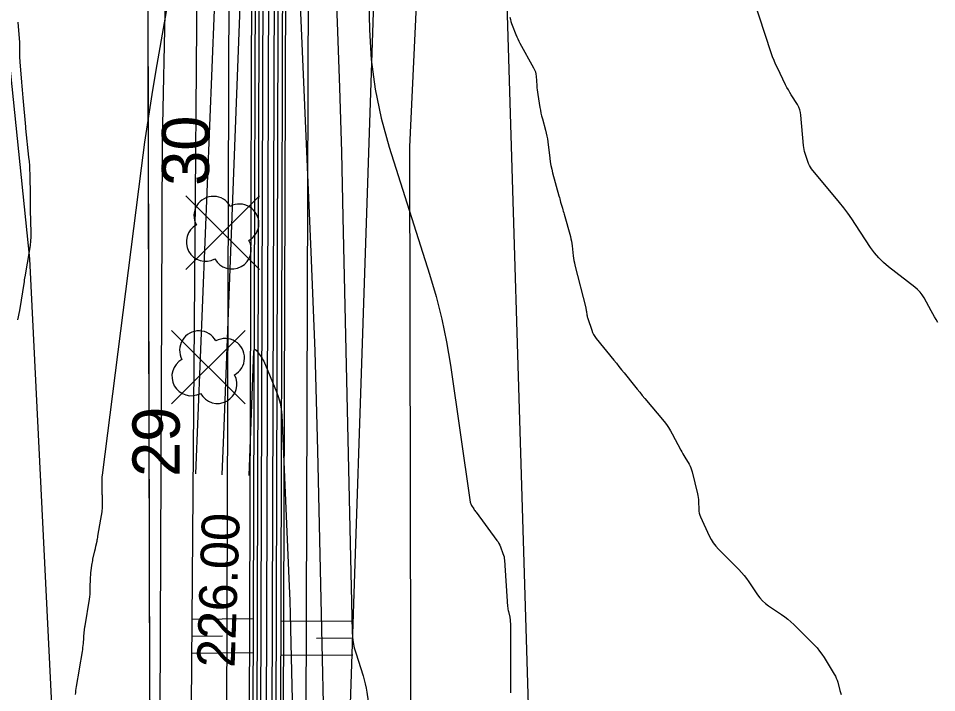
# Model space of a CAD drawing. Extents: x -534410 to -534262, y -1190162 to -1189584.
# Drawn here: x -534372.95 to -534348.66, y -1189778.79 to -1189760.95 of the extents above; entities that cross this region are included whole.
import ezdxf

# ---------------------------------------------------------------- set-up
doc = ezdxf.new("R2010")
doc.units = 0
for name, color, linetype in [('30', 7, 'Continuous'), ('31', 7, 'Continuous'), ('40', 7, 'Continuous'), ('_linie', 7, 'Continuous'), ('_N_osa', 7, 'Continuous'), ('_N_tenká', 7, 'Continuous'), ('_N_tenká_velmi', 7, 'Continuous'), ('_přístup', 7, 'Continuous'), ('_tenka', 7, 'Continuous'), ('_velmi_tenka', 7, 'Continuous'), ('Default', 7, 'Continuous'), ('Hranice parcel', 7, 'Continuous')]:
    doc.layers.add(name, color=color, linetype=linetype)

msp = doc.modelspace()

# ---------------------------------------------------------------- linework, layer by layer
at = {"layer": '30'}
for points in [[(-534367.558, -1189773.027), (-534367.512, -1189771.753), (-534366.662, -1189749.511), (-534366.647, -1189749.405), (-534366.611, -1189749.36), (-534366.556, -1189749.375), (-534366.481, -1189749.452), (-534365.983, -1189750.077), (-534365.978, -1189750.084), (-534365.973, -1189750.092), (-534365.968, -1189750.1), (-534365.964, -1189750.108), (-534365.95, -1189750.142), (-534365.947, -1189750.15), (-534365.945, -1189750.159), (-534365.943, -1189750.168), (-534365.943, -1189750.177), (-534365.213, -1189767.124), (-534365.16, -1189768.439), (-534365.113, -1189769.753), (-534365.074, -1189771.067), (-534365.041, -1189772.382), (-534364.917, -1189777.897), (-534364.89, -1189779.084)], [(-534363.748, -1189757.443), (-534363.663, -1189761.251), (-534363.617, -1189762.041), (-534363.516, -1189762.822), (-534363.358, -1189763.593), (-534363.145, -1189764.355), (-534362.075, -1189767.718), (-534361.899, -1189768.311), (-534361.749, -1189768.91), (-534361.623, -1189769.514), (-534361.522, -1189770.124), (-534360.997, -1189773.751), (-534360.992, -1189773.776), (-534360.984, -1189773.801), (-534360.974, -1189773.824), (-534360.961, -1189773.846), (-534360.903, -1189773.932), (-534360.889, -1189773.954), (-534360.874, -1189773.975), (-534360.859, -1189773.997), (-534360.843, -1189774.018), (-534360.289, -1189774.768), (-534360.262, -1189774.807), (-534360.238, -1189774.848), (-534360.217, -1189774.889), (-534360.199, -1189774.933), (-534360.131, -1189775.109), (-534360.115, -1189775.154), (-534360.103, -1189775.199), (-534360.095, -1189775.245), (-534360.09, -1189775.292), (-534360.007, -1189776.519), (-534360.004, -1189776.552), (-534360, -1189776.585), (-534359.994, -1189776.617), (-534359.987, -1189776.65), (-534359.951, -1189776.798), (-534359.946, -1189776.821), (-534359.942, -1189776.845), (-534359.94, -1189776.869), (-534359.939, -1189776.893), (-534359.936, -1189776.989), (-534359.936, -1189777.013), (-534359.935, -1189777.037), (-534359.935, -1189777.061), (-534359.935, -1189777.085), (-534359.935, -1189778.604), (-534359.935, -1189778.628), (-534359.935, -1189778.652), (-534359.935, -1189778.676), (-534359.934, -1189778.7), (-534359.932, -1189778.799)], [(-534371.442, -1189778.847), (-534371.437, -1189778.793), (-534371.43, -1189778.739), (-534371.423, -1189778.686), (-534371.414, -1189778.632), (-534371.339, -1189778.173), (-534371.338, -1189778.167), (-534371.26, -1189777.71), (-534371.251, -1189777.656), (-534371.244, -1189777.601), (-534371.238, -1189777.546), (-534371.233, -1189777.491), (-534371.21, -1189777.187), (-534371.209, -1189777.174), (-534371.208, -1189777.161), (-534371.206, -1189777.147), (-534371.204, -1189777.134), (-534371.191, -1189777.055), (-534371.187, -1189777.028), (-534371.075, -1189776.323), (-534371.065, -1189776.256), (-534371.058, -1189776.19), (-534371.053, -1189776.123), (-534371.05, -1189776.056), (-534371.041, -1189775.731), (-534371.04, -1189775.692), (-534371.037, -1189775.652), (-534371.034, -1189775.613), (-534371.029, -1189775.574), (-534371.008, -1189775.417), (-534371.002, -1189775.378), (-534370.996, -1189775.339), (-534370.988, -1189775.3), (-534370.98, -1189775.262), (-534370.931, -1189775.044), (-534370.917, -1189774.98), (-534370.902, -1189774.915), (-534370.873, -1189774.786), (-534370.866, -1189774.754), (-534370.859, -1189774.721), (-534370.853, -1189774.689), (-534370.847, -1189774.656), (-534370.798, -1189774.351), (-534370.795, -1189774.334), (-534370.792, -1189774.314), (-534370.79, -1189774.301), (-534370.741, -1189774.013), (-534370.734, -1189773.969), (-534370.73, -1189773.926), (-534370.727, -1189773.882), (-534370.727, -1189773.838), (-534370.732, -1189773.596), (-534370.732, -1189773.573), (-534370.733, -1189773.551), (-534370.733, -1189773.506), (-534370.733, -1189773.484), (-534370.733, -1189773.462), (-534370.738, -1189773.219), (-534370.738, -1189773.175), (-534370.737, -1189773.131), (-534370.734, -1189773.087), (-534370.729, -1189773.043), (-534369.696, -1189764.915), (-534369.604, -1189764.226), (-534369.504, -1189763.539), (-534369.396, -1189762.853), (-534369.28, -1189762.169), (-534368.697, -1189758.85)], [(-534348.626, -1189768.999), (-534348.67, -1189768.922), (-534348.714, -1189768.844), (-534348.757, -1189768.766), (-534348.8, -1189768.689), (-534348.989, -1189768.347), (-534349.038, -1189768.268), (-534349.095, -1189768.194), (-534349.159, -1189768.127), (-534349.23, -1189768.066), (-534349.927, -1189767.528), (-534350.062, -1189767.414), (-534350.187, -1189767.29), (-534350.3, -1189767.156), (-534350.403, -1189767.011), (-534350.799, -1189766.401), (-534350.9, -1189766.251), (-534351.004, -1189766.104), (-534351.113, -1189765.96), (-534351.227, -1189765.819), (-534351.963, -1189764.93), (-534351.996, -1189764.886), (-534352.024, -1189764.839), (-534352.048, -1189764.79), (-534352.067, -1189764.739), (-534352.134, -1189764.527), (-534352.149, -1189764.473), (-534352.161, -1189764.42), (-534352.17, -1189764.365), (-534352.177, -1189764.31), (-534352.246, -1189763.513), (-534352.257, -1189763.438), (-534352.276, -1189763.366), (-534352.304, -1189763.298), (-534352.341, -1189763.232), (-534352.503, -1189762.974), (-534352.542, -1189762.909), (-534352.58, -1189762.843), (-534352.616, -1189762.776), (-534352.651, -1189762.708), (-534352.87, -1189762.261), (-534352.916, -1189762.163), (-534352.958, -1189762.064), (-534352.997, -1189761.963), (-534353.033, -1189761.861), (-534353.994, -1189758.911)]]:
    msp.add_lwpolyline(points, dxfattribs=at)
at = {"layer": '31'}
for points in [[(-534365.123, -1189746.489), (-534365.076, -1189747.773), (-534365.028, -1189749.058), (-534364.976, -1189750.342), (-534364.922, -1189751.626), (-534364.59, -1189759.346), (-534364.52, -1189761.061), (-534364.46, -1189762.776), (-534364.408, -1189764.492), (-534364.365, -1189766.207), (-534364.12, -1189777.185), (-534364.111, -1189777.327), (-534364.093, -1189777.468), (-534364.065, -1189777.607), (-534364.026, -1189777.744), (-534363.833, -1189778.351), (-534363.802, -1189778.458), (-534363.774, -1189778.566), (-534363.752, -1189778.675), (-534363.733, -1189778.785), (-534363.639, -1189779.439)], [(-534368.254, -1189773.003), (-534367.398, -1189751.502), (-534367.341, -1189750.144), (-534367.279, -1189748.788), (-534367.241, -1189748.042)], [(-534359.946, -1189760.921), (-534359.936, -1189760.975), (-534359.923, -1189761.029), (-534359.907, -1189761.081), (-534359.888, -1189761.133), (-534359.79, -1189761.378), (-534359.765, -1189761.436), (-534359.74, -1189761.493), (-534359.712, -1189761.548), (-534359.682, -1189761.603), (-534359.319, -1189762.256), (-534359.293, -1189762.31), (-534359.273, -1189762.365), (-534359.259, -1189762.423), (-534359.252, -1189762.482), (-534359.236, -1189762.724), (-534359.231, -1189762.784), (-534359.225, -1189762.844), (-534359.218, -1189762.904), (-534359.209, -1189762.964), (-534359.155, -1189763.304), (-534359.142, -1189763.38), (-534359.126, -1189763.456), (-534359.108, -1189763.532), (-534359.089, -1189763.606), (-534359.003, -1189763.911), (-534358.984, -1189763.987), (-534358.967, -1189764.063), (-534358.953, -1189764.141), (-534358.942, -1189764.218), (-534358.891, -1189764.649), (-534358.878, -1189764.746), (-534358.861, -1189764.843), (-534358.841, -1189764.939), (-534358.817, -1189765.035), (-534358.65, -1189765.648), (-534358.639, -1189765.689), (-534358.628, -1189765.729), (-534358.616, -1189765.77), (-534358.605, -1189765.81), (-534358.558, -1189765.972), (-534358.546, -1189766.013), (-534358.534, -1189766.053), (-534358.523, -1189766.094), (-534358.512, -1189766.135), (-534358.348, -1189766.72), (-534358.332, -1189766.782), (-534358.319, -1189766.845), (-534358.308, -1189766.909), (-534358.299, -1189766.973), (-534358.271, -1189767.23), (-534358.263, -1189767.294), (-534358.253, -1189767.358), (-534358.24, -1189767.421), (-534358.226, -1189767.484), (-534357.942, -1189768.611), (-534357.936, -1189768.634), (-534357.932, -1189768.658), (-534357.927, -1189768.681), (-534357.924, -1189768.704), (-534357.91, -1189768.798), (-534357.907, -1189768.821), (-534357.902, -1189768.844), (-534357.896, -1189768.867), (-534357.889, -1189768.889), (-534357.783, -1189769.202), (-534357.761, -1189769.26), (-534357.733, -1189769.316), (-534357.701, -1189769.369), (-534357.664, -1189769.419), (-534357.198, -1189769.992), (-534357.13, -1189770.077), (-534357.061, -1189770.162), (-534356.992, -1189770.247), (-534356.924, -1189770.333), (-534356.65, -1189770.674), (-534356.582, -1189770.759), (-534356.513, -1189770.844), (-534356.444, -1189770.929), (-534356.374, -1189771.013), (-534355.869, -1189771.622), (-534355.808, -1189771.7), (-534355.751, -1189771.78), (-534355.699, -1189771.863), (-534355.65, -1189771.949), (-534355.421, -1189772.376), (-534355.396, -1189772.424), (-534355.369, -1189772.471), (-534355.343, -1189772.518), (-534355.316, -1189772.565), (-534355.206, -1189772.751), (-534355.181, -1189772.799), (-534355.159, -1189772.847), (-534355.14, -1189772.898), (-534355.125, -1189772.949), (-534354.982, -1189773.529), (-534354.971, -1189773.58), (-534354.963, -1189773.631), (-534354.957, -1189773.683), (-534354.955, -1189773.735), (-534354.95, -1189773.945), (-534354.947, -1189773.996), (-534354.938, -1189774.047), (-534354.924, -1189774.096), (-534354.904, -1189774.145), (-534354.674, -1189774.646), (-534354.625, -1189774.742), (-534354.567, -1189774.833), (-534354.502, -1189774.919), (-534354.429, -1189774.999), (-534353.891, -1189775.537), (-534353.819, -1189775.612), (-534353.751, -1189775.691), (-534353.687, -1189775.773), (-534353.627, -1189775.858), (-534353.394, -1189776.206), (-534353.332, -1189776.289), (-534353.263, -1189776.365), (-534353.187, -1189776.434), (-534353.104, -1189776.495), (-534352.757, -1189776.728), (-534352.672, -1189776.788), (-534352.59, -1189776.852), (-534352.511, -1189776.92), (-534352.436, -1189776.992), (-534351.892, -1189777.536), (-534351.82, -1189777.612), (-534351.753, -1189777.693), (-534351.691, -1189777.777), (-534351.633, -1189777.865), (-534351.363, -1189778.308), (-534351.335, -1189778.358), (-534351.311, -1189778.409), (-534351.291, -1189778.461), (-534351.274, -1189778.515), (-534351.214, -1189778.735), (-534351.2, -1189778.79), (-534351.186, -1189778.845)], [(-534372.965, -1189768.926), (-534372.949, -1189768.844), (-534372.933, -1189768.762), (-534372.919, -1189768.68), (-534372.794, -1189767.913), (-534372.791, -1189767.892), (-534372.788, -1189767.871), (-534372.782, -1189767.829), (-534372.779, -1189767.808), (-534372.776, -1189767.787), (-534372.65, -1189767.063), (-534372.634, -1189766.954), (-534372.623, -1189766.844), (-534372.618, -1189766.733), (-534372.617, -1189766.623), (-534372.629, -1189766.014), (-534372.63, -1189765.985), (-534372.63, -1189765.957), (-534372.63, -1189765.929), (-534372.63, -1189765.901), (-534372.631, -1189765.789), (-534372.631, -1189765.761), (-534372.631, -1189765.733), (-534372.632, -1189765.705), (-534372.632, -1189765.676), (-534372.645, -1189765.067), (-534372.648, -1189764.956), (-534372.654, -1189764.845), (-534372.663, -1189764.734), (-534372.674, -1189764.624), (-534372.758, -1189763.868), (-534372.758, -1189763.86), (-534372.758, -1189763.852), (-534372.759, -1189763.833), (-534372.759, -1189763.825), (-534372.759, -1189763.821), (-534372.829, -1189763.052), (-534372.838, -1189762.948), (-534372.847, -1189762.844), (-534372.856, -1189762.741), (-534372.864, -1189762.637), (-534372.906, -1189762.098), (-534372.909, -1189762.056), (-534372.911, -1189762.014), (-534372.912, -1189761.972), (-534372.913, -1189761.929), (-534372.913, -1189761.76), (-534372.913, -1189761.717), (-534372.914, -1189761.675), (-534372.916, -1189761.633), (-534372.918, -1189761.59), (-534372.955, -1189761.052)], [(-534366.847, -1189773.051), (-534366.721, -1189769.754), (-534366.716, -1189769.719), (-534366.705, -1189769.705), (-534366.687, -1189769.71), (-534366.663, -1189769.734), (-534366.553, -1189769.873), (-534366.526, -1189769.908), (-534366.503, -1189769.945), (-534366.482, -1189769.983), (-534366.463, -1189770.023), (-534366.123, -1189770.834), (-534366.067, -1189770.984), (-534366.026, -1189771.137), (-534365.998, -1189771.294), (-534365.984, -1189771.453), (-534365.789, -1189775.978), (-534365.774, -1189776.354), (-534365.761, -1189776.729), (-534365.75, -1189777.105), (-534365.74, -1189777.481), (-534365.707, -1189778.983)]]:
    msp.add_lwpolyline(points, dxfattribs=at)
at = {"layer": '_linie'}
for points in [[(-534366.12, -1189620.81), (-534364.52, -1189627.2), (-534365.69, -1189653.8), (-534366.76, -1189684.81), (-534368.14, -1189748.73), (-534368.38, -1189779.14), (-534368.65, -1189820.64), (-534368.59, -1189847.58), (-534367.2, -1189913.8)], [(-534363.12, -1189621.02), (-534362.79, -1189621.58), (-534361.82, -1189627.79), (-534363.46, -1189653.55), (-534365.47, -1189684.77), (-534366.65, -1189748.83), (-534366.75, -1189779.47), (-534366.9, -1189820.47), (-534366.95, -1189846.72), (-534366.338, -1189888.804), (-534363.85, -1189911.95), (-534357.07, -1189929.19), (-534352.334, -1189940.856)], [(-534359.03, -1189621.26), (-534359.41, -1189621.83), (-534360.84, -1189627.76), (-534362.92, -1189653.56), (-534364.64, -1189685), (-534365.94, -1189748.9), (-534366.02, -1189779.52), (-534366.03, -1189820.5), (-534366.48, -1189846.73), (-534365.511, -1189888.873), (-534362.72, -1189912.12), (-534356.62, -1189928.64), (-534351.589, -1189940.594)]]:
    msp.add_lwpolyline(points, dxfattribs=at)
at = {"layer": '_N_osa'}
msp.add_lwpolyline([(-534351.95, -1189940.722), (-534356.845, -1189928.915), (-534363.285, -1189912.035), (-534365.925, -1189888.838), (-534366.715, -1189846.725), (-534366.465, -1189820.485), (-534366.385, -1189779.495), (-534366.295, -1189748.865), (-534365.055, -1189684.885), (-534363.19, -1189653.555), (-534361.333, -1189627.822)], dxfattribs=at)
at = {"layer": '_N_tenká'}
for points in [[(-534352.92, -1189941.124), (-534357.821, -1189929.303), (-534364.313, -1189912.285), (-534366.973, -1189888.908), (-534367.765, -1189846.73), (-534367.515, -1189820.479), (-534367.435, -1189779.492), (-534367.345, -1189748.853), (-534366.104, -1189684.844), (-534364.238, -1189653.486), (-534362.424, -1189628.352), (-534361.782, -1189627.792)], [(-534350.98, -1189940.319), (-534355.869, -1189928.527), (-534362.257, -1189911.785), (-534364.876, -1189888.769), (-534365.665, -1189846.72), (-534365.415, -1189820.491), (-534365.335, -1189779.498), (-534365.245, -1189748.877), (-534364.006, -1189684.926), (-534362.142, -1189653.624), (-534360.329, -1189628.488), (-534360.884, -1189627.851)]]:
    msp.add_lwpolyline(points, dxfattribs=at)
at = {"layer": '_N_tenká_velmi'}
for points in [[(-534352.366, -1189940.894), (-534357.263, -1189929.081), (-534363.726, -1189912.142), (-534366.374, -1189888.868), (-534367.165, -1189846.727), (-534366.915, -1189820.482), (-534366.835, -1189779.494), (-534366.745, -1189748.86), (-534365.505, -1189684.867), (-534363.639, -1189653.525), (-534361.782, -1189627.792)], [(-534352.181, -1189940.817), (-534357.077, -1189929.007), (-534363.53, -1189912.095), (-534366.174, -1189888.855), (-534366.965, -1189846.726), (-534366.715, -1189820.484), (-534366.635, -1189779.494), (-534366.545, -1189748.862), (-534365.305, -1189684.875), (-534363.439, -1189653.539), (-534361.583, -1189627.805)], [(-534352.089, -1189940.779), (-534356.984, -1189928.97), (-534363.432, -1189912.071), (-534366.074, -1189888.848), (-534366.865, -1189846.726), (-534366.615, -1189820.484), (-534366.535, -1189779.495), (-534366.445, -1189748.863), (-534365.205, -1189684.879), (-534363.34, -1189653.545), (-534361.483, -1189627.812)], [(-534351.812, -1189940.664), (-534356.706, -1189928.86), (-534363.138, -1189911.999), (-534365.775, -1189888.828), (-534366.565, -1189846.724), (-534366.315, -1189820.486), (-534366.235, -1189779.495), (-534366.145, -1189748.867), (-534364.905, -1189684.891), (-534363.04, -1189653.565), (-534361.184, -1189627.831)], [(-534351.719, -1189940.626), (-534356.613, -1189928.823), (-534363.04, -1189911.975), (-534365.675, -1189888.822), (-534366.465, -1189846.724), (-534366.215, -1189820.486), (-534366.135, -1189779.496), (-534366.045, -1189748.868), (-534364.805, -1189684.895), (-534362.941, -1189653.571), (-534361.084, -1189627.838)], [(-534351.534, -1189940.549), (-534356.427, -1189928.749), (-534362.844, -1189911.928), (-534365.475, -1189888.808), (-534366.265, -1189846.723), (-534366.015, -1189820.488), (-534365.935, -1189779.496), (-534365.845, -1189748.87), (-534364.605, -1189684.903), (-534362.741, -1189653.585), (-534360.884, -1189627.851)]]:
    msp.add_lwpolyline(points, dxfattribs=at)
at = {"layer": '_přístup'}
for p, q in [((-534366.577, -1189767.593), (-534368.523, -1189765.647)), ((-534368.523, -1189767.593), (-534366.577, -1189765.647)), ((-534366.957, -1189771.153), (-534368.903, -1189769.207)), ((-534368.903, -1189771.153), (-534366.957, -1189769.207))]:
    msp.add_line(p, q, dxfattribs=at)
for centre in [(-534367.55, -1189766.62), (-534367.93, -1189770.18)]:
    msp.add_circle(centre, 0.000512, dxfattribs=at)
for centre, start, end in [((-534367.795, -1189766.171), 28.6209, 208.6209), ((-534367.101, -1189766.375), 298.6209, 118.6209), ((-534367.999, -1189766.865), 118.6209, 298.6209), ((-534367.305, -1189767.069), 208.6209, 28.6209), ((-534368.175, -1189769.731), 28.6209, 208.6209), ((-534367.481, -1189769.935), 298.6209, 118.6209), ((-534368.379, -1189770.425), 118.6209, 298.6209), ((-534367.685, -1189770.629), 208.6209, 28.6209)]:
    msp.add_arc(centre, 0.512, start, end, dxfattribs=at)
at = {"layer": '_tenka'}
for points in [[(-534349.13, -1189939.73), (-534354.63, -1189926.96), (-534362.03, -1189907.65), (-534364.521, -1189888.74), (-534364.47, -1189846.64), (-534364.29, -1189820.63), (-534364.22, -1189780.69), (-534363.18, -1189749.38), (-534362.5, -1189685.39), (-534360.27, -1189651.6), (-534357.03, -1189627.34), (-534354.77, -1189620.37)], [(-534366.12, -1189620.81), (-534364.52, -1189627.2), (-534365.69, -1189653.8), (-534366.76, -1189684.81), (-534368.14, -1189748.73), (-534368.38, -1189779.14), (-534368.65, -1189820.64), (-534368.59, -1189847.58), (-534367.2, -1189913.8)], [(-534366.12, -1189620.81), (-534364.52, -1189627.2), (-534365.69, -1189653.8), (-534366.76, -1189684.81), (-534368.14, -1189748.73), (-534368.38, -1189779.14), (-534368.65, -1189820.64), (-534368.59, -1189847.58), (-534367.2, -1189913.8)], [(-534363.12, -1189621.02), (-534362.79, -1189621.58), (-534361.82, -1189627.79), (-534363.46, -1189653.55), (-534365.47, -1189684.77), (-534366.65, -1189748.83), (-534366.75, -1189779.47), (-534366.9, -1189820.47), (-534366.95, -1189846.72), (-534366.338, -1189888.804), (-534363.85, -1189911.95), (-534357.07, -1189929.19), (-534352.334, -1189940.856)], [(-534363.12, -1189621.02), (-534362.79, -1189621.58), (-534361.82, -1189627.79), (-534363.46, -1189653.55), (-534365.47, -1189684.77), (-534366.65, -1189748.83), (-534366.75, -1189779.47), (-534366.9, -1189820.47), (-534366.95, -1189846.72), (-534366.338, -1189888.804), (-534363.85, -1189911.95), (-534357.07, -1189929.19), (-534352.334, -1189940.856)], [(-534359.03, -1189621.26), (-534359.41, -1189621.83), (-534360.84, -1189627.76), (-534362.92, -1189653.56), (-534364.64, -1189685), (-534365.94, -1189748.9), (-534366.02, -1189779.52), (-534366.03, -1189820.5), (-534366.48, -1189846.73), (-534365.511, -1189888.873), (-534362.72, -1189912.12), (-534356.62, -1189928.64), (-534351.589, -1189940.594)], [(-534359.03, -1189621.26), (-534359.41, -1189621.83), (-534360.84, -1189627.76), (-534362.92, -1189653.56), (-534364.64, -1189685), (-534365.94, -1189748.9), (-534366.02, -1189779.52), (-534366.03, -1189820.5), (-534366.48, -1189846.73), (-534365.511, -1189888.873), (-534362.72, -1189912.12), (-534356.62, -1189928.64), (-534351.589, -1189940.594)], [(-534368.65, -1189626.81), (-534368.65, -1189626.81), (-534367.31, -1189654.04), (-534367.67, -1189685.23), (-534369.56, -1189748.93), (-534369.48, -1189778.6), (-534369.45, -1189820.62), (-534369.45, -1189847.87), (-534371.206, -1189896.071), (-534372.39, -1189914.47)]]:
    msp.add_lwpolyline(points, dxfattribs=at)
at = {"layer": '_velmi_tenka'}
for p, q in [((-534368.369, -1189776.846), (-534366.747, -1189776.831)), ((-534364.112, -1189776.902), (-534366.017, -1189776.914)), ((-534368.365, -1189777.296), (-534367.554, -1189777.288)), ((-534364.109, -1189777.352), (-534365.062, -1189777.358)), ((-534368.361, -1189777.746), (-534366.739, -1189777.731)), ((-534364.106, -1189777.802), (-534366.012, -1189777.814))]:
    msp.add_line(p, q, dxfattribs=at)
at = {"layer": 'Default'}
for p, q in [((-534369.56, -1189748.93), (-534369.48, -1189778.6)), ((-534369.48, -1189778.6), (-534369.45, -1189820.62))]:
    msp.add_line(p, q, dxfattribs=at)
msp.add_lwpolyline([(-534349.13, -1189939.73), (-534354.63, -1189926.96), (-534362.03, -1189907.65), (-534364.521, -1189888.74), (-534364.47, -1189846.64), (-534364.29, -1189820.63), (-534364.22, -1189780.69), (-534363.18, -1189749.38), (-534362.5, -1189685.39), (-534360.27, -1189651.6), (-534357.03, -1189627.34), (-534354.77, -1189620.37)], dxfattribs=at)
at = {"layer": 'Hranice parcel'}
for p, q in [((-534369.14, -1189764.19), (-534367.77, -1189697.34)), ((-534369.38, -1189820.8), (-534369.14, -1189764.19))]:
    msp.add_line(p, q, dxfattribs=at)
for points in [[(-534359.48, -1189697.97), (-534362.6, -1189764.35), (-534362.34, -1189901.56)], [(-534359.48, -1189697.97), (-534360.42, -1189747.8), (-534359.17, -1189788.69), (-534356.86, -1189843.2), (-534358.53, -1189915.98)], [(-534369.38, -1189820.8), (-534370.35, -1189813.98), (-534372.65, -1189767.31), (-534373.49, -1189759.21)]]:
    msp.add_lwpolyline(points, dxfattribs=at)

# ---------------------------------------------------------------- texts
at = {"layer": '40'}
msp.add_text('226.00', height=1, rotation=88.0426, dxfattribs=at).set_placement((-534367.233, -1189778.143))
at = {"layer": '_přístup'}
for s, p in [('30', (-534367.907, -1189765.382)), ('29', (-534368.686, -1189773.086))]:
    msp.add_text(s, height=1.25, rotation=90, dxfattribs=at).set_placement(p)

doc.saveas('drawing.dxf')
